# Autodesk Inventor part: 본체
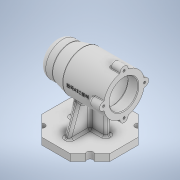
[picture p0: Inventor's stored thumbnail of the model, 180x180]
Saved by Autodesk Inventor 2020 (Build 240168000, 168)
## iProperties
Created: 2021-01
Part Number: 본체
Material: 일반
Document SubType Name: Modeling
Designer: pc-05
Density: 1 g/cm^3
Appearance: 기본값
Author: pc-05
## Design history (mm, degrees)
sketch "스케치1"
  geometry: L1 (-20.711, -50)-(-50, -20.711); L2 (-50, -20.711)-(-50, 20.711); L3 (-50, 20.711)-(-20.711, 50); L4 (-20.711, 50)-(20.711, 50); L5 (20.711, 50)-(50, 20.711); L6 (50, 20.711)-(50, -20.711); L7 (50, -20.711)-(20.711, -50); L8 (20.711, -50)-(-20.711, -50); L9 (35.355, -35.355)-(-35.355, 35.355); L10 (-35.355, -35.355)-(35.355, 35.355); C1 r 4.5 at (35.355, -35.355); C2 r 4.5 at (-35.355, -35.355); C3 r 4.5 at (-35.355, 35.355); C4 r 4.5 at (35.355, 35.355); 12 further points
  constraints: 20 end point, 6 coincident, 5 midpoint, 4 centre point, 1 vertical alignment, 20 other
  dimensions: "d0" = 50 horizontal distance of L1.end point (0, -50); "d1" = 9 diameter of C1; "d2" = 9 diameter of C2; "d3" = 9 diameter of C4; "d4" = 9 diameter of C3
extrude "돌출1" new body sketch "스케치1" distance "d5" = 10; taper "d6" = 0 deg
sketch "스케치2"
  geometry: L1 (-50, 75)-(50, 75); L2 (50, 0)-(38.537, 0) reference; L3 (-50, 75)-(-50, 100); L4 (-50, 100)-(-30, 100); L5 (-30, 100)-(-10, 105); L6 (-10, 105)-(50, 105); L7 (50, 105)-(50, 75); L8 (-44, 75)-(-44, 85.5); L9 (-44, 85.5)-(-41, 85.5); L10 (-41, 85.5)-(-41, 91); L11 (-41, 91)-(-37, 91); L12 (-37, 91)-(-37, 92.5); L13 (-37, 92.5)-(-19, 92.5); L14 (-19, 92.5)-(-19, 96); L15 (-19, 96)-(-7, 96); L16 (-7, 96)-(-7, 99); L17 (-7, 99)-(35, 99); L18 (35, 99)-(35, 96); L19 (35, 96)-(50, 96); 1 further point
  constraints: 36 end point, 12 perpendicular, 2 horizontal, 2 point on line, 2 vertical, 1 parallel, 1 vertical alignment
  dimensions: "d7" = 75 distance from line of L2 L1.end; "d8" = 50 diameter of L4 L1; "d9" = 60 diameter of L5.end L1; "d10" = 20 distance of L3.end L4.end; "d11" = 40 horizontal distance of L3.end L5.end; "d12" = 100 horizontal distance of L3.end L6.end; "d13" = 21 diameter of L9 L1; "d14" = 3 distance of L8.end L9.end; "d15" = 32 diameter of L11 L1; "d16" = 4 distance of L10.end L11.end; "d17" = 35 diameter of L13 L1; "d18" = 18 distance of L12.end L13.end; "d19" = 42 diameter of L15 L1; "d20" = 12 distance of L14.end L15.end; "d21" = 42 distance of L16.end L17.end; "d22" = 48 diameter of L17 L1; "d23" = 15 distance of L18.end L19.end; "d24" = 42 diameter of L19 L1
revolve "회전1" sketch "스케치2" stored, may be unused: angle "d25" = 90 deg
fillet "모깎기1" dims "d26" = 10
fillet "모깎기2" dims "d27" = 3
fillet "모깎기3" dims "d28" = 3
fillet "모깎기4" dims "d29" = 0.3
fillet "모깎기5" dims "d30" = 3
chamfer "모따기1" distance "d31" = 1; stored, may be unused: second distance "d32" = 2, angle "d33" = 45 deg
sketch "스케치3"
  geometry: L1 (-29.642, 49.91)-(-10.358, 45.09) reference; L2 (-50, 0)-(-50, 10) reference; L3 (-20.711, 10)-(-32.173, 10) reference; L4 (-9.631, 45)-(50, 45) reference; L5 (27, 45)-(27, 10); L6 (50, 0)-(50, 10) reference; L7 (-19.724, 47.431)-(-27, 10); L8 (-38.537, 10)-(-50, 10) reference; L9 (20.711, 10)-(-20.711, 10) reference; L10 (32.173, 10)-(20.711, 10) reference; L11 (-19.724, 47.431)-(-19.313, 49.91); L12 (-19.313, 49.91)-(27, 49.91); L13 (27, 49.91)-(27, 45); A1 r 3 centre (-9.631, 48) between (-10.358, 45.09) and (-9.631, 45) reference; 1 further point
  constraints: 10 end point, 4 point on line, 1 perpendicular, 1 vertical
  dimensions: "d39" = 23 horizontal distance of L6.start L5.end; "d41" = 23 horizontal distance of L2.start L7.end; "d42" = 101 deg angle of L8 L7; "d43" = 4.91043 distance of L12.end L5.start; "d44" = 46.31348 distance of L11.end L12.end; "d45" = 99.4045 deg angle of L12 L11
extrude "돌출2" join sketch "스케치3" stored distance "d46" = 8; taper "d47" = 0 deg
sketch "스케치4"
  geometry: L1 (52.293, 19.606)-(10, 35); L2 (10, 20.711)-(10, 32.173) reference; L3 (10, -32.173)-(10, -20.711) reference; L4 (0, 50)-(10, 50) reference; L5 (52.293, -19.606)-(10, -35); L6 (0, -50)-(10, -50) reference; L7 (10, -50)-(10, -38.537) reference; L8 (10, 38.537)-(10, 50) reference; L9 (10, 38.537)-(10, 30.855) reference; L10 (10, -20.711)-(10, 20.711) reference; L11 (10, -30.855)-(10, -38.537) reference; L12 (47.431, 4)-(10, 4) reference; L13 (10, -4)-(47.431, -4) reference; A1 r 30 centre (75, 0) between (45.268, -4) and (45.268, 4) reference; 1 further point
  constraints: 4 end point, 2 point on circle, 2 point on line
  dimensions: "d48" = 15 distance from line of L4 L1.end; "d49" = 15 distance from line of L6 L5.end; "d50" = 110 deg angle of L7 L5; "d51" = 110 deg angle of L8 L1
extrude "돌출3" join sketch "스케치4" stored distance "d52" = 8; taper "d53" = 0 deg
sketch "스케치5"
  geometry: A1 r 30 centre (0, 0) between (0, 30) and (-5.97, 29.4) reference; A2 r 6 centre (0, 30) between (5.97, 29.4) and (-5.97, 29.4); 1 further point
  constraints: 5 point on circle, 1 centre point
  dimensions: "d54" = 6 radius of A2
extrude "돌출4" join sketch "스케치5" distance "d55" = 16; taper "d56" = 0 deg
sketch "스케치6"
  geometry: A1 r 6 centre (0, 0) between (5.97, -0.6) and (-5.97, -0.6) reference; 2 further points
  constraints: 1 coincident
hole "구멍1" sketch "스케치6" at (0, 0) diameter "d60" = 3.242; stored, may be unused: countersink angle "d64" = 90 deg, drill point angle "d66" = 118 deg; dims "d61" = 8, "d62" = 4, "d63" = 2, "d65" = 10
fillet "모깎기6" dims "d70" = 3
fillet "모깎기7" dims "d71" = 3
fillet "모깎기8" dims "d72" = 3
fillet "모깎기9" dims "d73" = 3
fillet "모깎기10" dims "d74" = 3
fillet "모깎기11" dims "d75" = 3
fillet "모깎기12" dims "d76" = 1
node "작업 평면1"
sketch "스케치7"
  geometry: L1 (50, 69.002)-(50, 80.998) reference; L2 (50, 105.171)-(50, 111) reference; 3 further points
  constraints: 1 horizontal alignment, 1 midpoint, 1 other
  dimensions: "d78" = 38 distance from line of L2 point (12, 75)
feature "엠보싱1" sketch "스케치7" dims "d0" = 50, "d1" = 9, "d2" = 9, "d3" = 9, "d4" = 9, "d79" = 0.5, "d80" = 0
node "솔리드1"
pattern_circular "원형 패턴1" dims angle "d58" = 360 deg
pattern_circular "원형 패턴2" dims angle "d68" = 360 deg
feature "A9D066F2-1C7D-4E18-AEED-F7BC21143FA4" dims "d60" = 3.242, "d61" = 8, "d62" = 4, "d63" = 2, "d64" = 90 deg, "d65" = 10, "d66" = 118 deg
